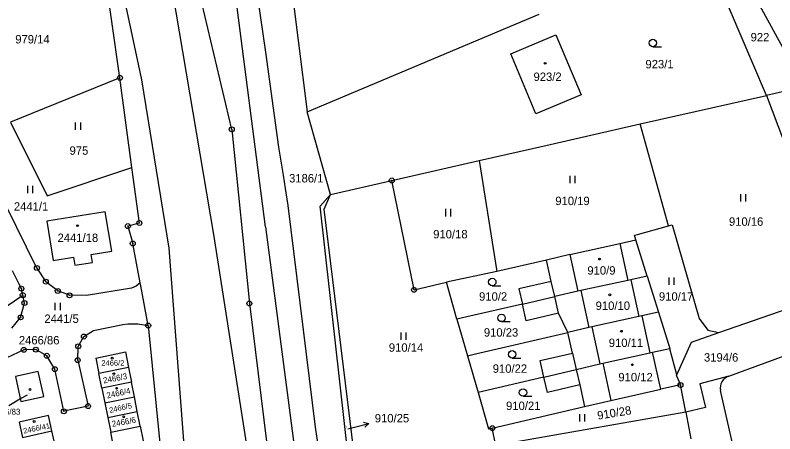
# Model space of a CAD drawing. Extents: x -736345 to -729997, y -1130177 to -1122501.
# Drawn here: x -733345 to -733191.4, y -1127571.2 to -1127486.6 of the extents above; entities that cross this region are included whole.
import ezdxf

# ---------------------------------------------------------------- set-up
doc = ezdxf.new("R2010")
doc.units = 0
for name, color, linetype in [('Vrstva 1', 7, 'Continuous'), ('Vrstva 10', 7, 'Continuous'), ('Vrstva 16', 7, 'Continuous'), ('Vrstva 18', 7, 'Continuous'), ('Vrstva 19', 7, 'Continuous'), ('Vrstva 25', 7, 'Continuous'), ('Vrstva 4', 7, 'Continuous')]:
    doc.layers.add(name, color=color, linetype=linetype)

msp = doc.modelspace()

# ---------------------------------------------------------------- linework, layer by layer
at = {"layer": 'Vrstva 1'}
for points in [[(-733301.2, -1127509.66), (-733310.3, -1127471.24)], [(-733200.3, -1127473.75), (-733185.45, -1127501.06)], [(-733323.81, -1127499.24), (-733327.23, -1127475.47)], [(-733294.28, -1127494.04), (-733296.98, -1127475.45)], [(-733195.81, -1127496.33), (-733204.85, -1127475.11)], [(-733289.62, -1127477.2), (-733285.95, -1127506.12)], [(-733285.95, -1127506.12), (-733239.06, -1127486.36)], [(-733244.79, -1127494.36), (-733235.65, -1127490.52)], [(-733235.65, -1127490.52), (-733230.53, -1127502.67)], [(-733291.7, -1127513.26), (-733294.28, -1127494.04)], [(-733239.67, -1127506.53), (-733244.79, -1127494.36)], [(-733193.06, -1127502.79), (-733195.81, -1127496.33)], [(-733323.81, -1127499.24), (-733341.66, -1127506.49)], [(-733321.39, -1127517.36), (-733323.81, -1127499.24)], [(-733185.45, -1127501.06), (-733193.06, -1127502.79)], [(-733230.53, -1127502.67), (-733239.67, -1127506.53)], [(-733218.57, -1127508.58), (-733193.06, -1127502.79)], [(-733193.06, -1127502.79), (-733178.14, -1127542.26)], [(-733341.66, -1127506.49), (-733345.96, -1127508.19)], [(-733281.24, -1127522.82), (-733285.95, -1127506.12)], [(-733345.96, -1127508.19), (-733338.54, -1127523.08)], [(-733237.7, -1127512.93), (-733218.57, -1127508.58)], [(-733212.85, -1127529.17), (-733218.57, -1127508.58)], [(-733301.2, -1127509.66), (-733297.64, -1127544.88)], [(-733290.75, -1127518.9), (-733291.7, -1127513.26)], [(-733251.18, -1127515.99), (-733237.7, -1127512.93)], [(-733340.6, -1127537.7), (-733351.02, -1127516.8)], [(-733268.83, -1127520), (-733251.18, -1127515.99)], [(-733251.18, -1127515.99), (-733247.58, -1127538.44)], [(-733338.54, -1127523.08), (-733321.39, -1127517.36)], [(-733319.88, -1127528.61), (-733321.39, -1127517.36)], [(-733290.33, -1127521.63), (-733290.75, -1127518.9)], [(-733281.24, -1127522.82), (-733268.83, -1127520)], [(-733264.34, -1127542.1), (-733268.83, -1127520)], [(-733289.76, -1127525.07), (-733290.33, -1127521.63)], [(-733283.29, -1127525.21), (-733281.24, -1127522.82)], [(-733282.53, -1127525.78), (-733281.24, -1127522.82)], [(-733326.79, -1127526.36), (-733338.6, -1127528.26)], [(-733325.47, -1127534.29), (-733326.79, -1127526.36)], [(-733284.29, -1127569.9), (-733289.76, -1127525.07)], [(-733277.3, -1127578.79), (-733283.29, -1127525.21)], [(-733276.02, -1127578.56), (-733282.53, -1127525.78)], [(-733338.6, -1127528.26), (-733337.32, -1127536.17)], [(-733319.88, -1127528.61), (-733322.2, -1127529.23)], [(-733322.2, -1127529.23), (-733321.22, -1127532.75)], [(-733219.11, -1127530.9), (-733212.85, -1127529.17)], [(-733212.85, -1127529.17), (-733212.14, -1127528.97)], [(-733212.14, -1127528.97), (-733206.65, -1127547.88)], [(-733219.76, -1127531.08), (-733219.11, -1127530.9)], [(-733219.47, -1127532.01), (-733219.76, -1127531.08)], [(-733222.7, -1127532.73), (-733219.47, -1127532.01)], [(-733217.18, -1127539.35), (-733219.47, -1127532.01)], [(-733319.72, -1127540.72), (-733321.22, -1127532.75)], [(-733232.8, -1127534.99), (-733222.7, -1127532.73)], [(-733337.32, -1127536.17), (-733333.17, -1127535.54)], [(-733333.17, -1127535.54), (-733332.93, -1127537.14)], [(-733329.61, -1127534.95), (-733325.47, -1127534.29)], [(-733329.35, -1127536.57), (-733329.61, -1127534.95)], [(-733232.8, -1127534.99), (-733237.55, -1127536.1)], [(-733332.93, -1127537.14), (-733329.35, -1127536.57)], [(-733237.55, -1127536.1), (-733247.58, -1127538.44)], [(-733236.57, -1127540.42), (-733237.55, -1127536.1)], [(-733344.18, -1127541), (-733345.53, -1127538.29)], [(-733340.6, -1127537.7), (-733338.8, -1127540.47)], [(-733247.58, -1127538.44), (-733257.79, -1127540.57)], [(-733221.07, -1127540.2), (-733230.6, -1127542.28)], [(-733220.48, -1127540.07), (-733221.07, -1127540.2)], [(-733217.18, -1127539.35), (-733220.48, -1127540.07)], [(-733217.18, -1127539.35), (-733214.9, -1127546.65)], [(-733343.75, -1127541.87), (-733344.18, -1127541)], [(-733343.46, -1127543.21), (-733343.75, -1127541.87)], [(-733336.38, -1127542.34), (-733338.8, -1127540.47)], [(-733321.45, -1127541.79), (-733330.57, -1127543.28)], [(-733320.53, -1127541.38), (-733321.45, -1127541.79)], [(-733319.72, -1127540.72), (-733320.53, -1127541.38)], [(-733319.6, -1127541.33), (-733319.72, -1127540.72)], [(-733318.09, -1127549.34), (-733319.6, -1127541.33)], [(-733264.34, -1127542.1), (-733257.79, -1127540.57)], [(-733255.65, -1127548.04), (-733257.79, -1127540.57)], [(-733236.57, -1127540.42), (-733243.12, -1127541.94)], [(-733357.22, -1127552.48), (-733343.46, -1127543.21)], [(-733343.13, -1127544.78), (-733343.46, -1127543.21)], [(-733334.01, -1127543.22), (-733336.38, -1127542.34)], [(-733330.57, -1127543.28), (-733334.01, -1127543.22)], [(-733243.12, -1127541.94), (-733242.43, -1127545)], [(-733231.18, -1127542.41), (-733235.87, -1127543.49)], [(-733230.6, -1127542.28), (-733231.18, -1127542.41)], [(-733202.72, -1127550.77), (-733178.14, -1127542.26)], [(-733343.89, -1127547.68), (-733343.13, -1127544.78)], [(-733297.64, -1127544.88), (-733292.42, -1127586.98)], [(-733242.43, -1127545), (-733235.87, -1127543.49)], [(-733242.43, -1127545), (-733253.65, -1127547.58)], [(-733241.66, -1127548.37), (-733242.43, -1127545)], [(-733200.69, -1127559.59), (-733163.94, -1127546.08)], [(-733345.65, -1127549.87), (-733343.89, -1127547.68)], [(-733253.65, -1127547.58), (-733255.65, -1127548.04)], [(-733255.65, -1127548.04), (-733253.52, -1127555.44)], [(-733235.1, -1127546.86), (-733241.66, -1127548.37)], [(-733233.23, -1127550.73), (-733235.1, -1127546.86)], [(-733218.85, -1127547.52), (-733228.38, -1127549.61)], [(-733218.27, -1127547.39), (-733218.85, -1127547.52)], [(-733214.9, -1127546.65), (-733218.27, -1127547.39)], [(-733214.9, -1127546.65), (-733212.62, -1127553.98)], [(-733206.65, -1127547.88), (-733204.93, -1127550.24)], [(-733329.17, -1127550.36), (-733323.21, -1127549.14)], [(-733323.21, -1127549.14), (-733322.2, -1127549)], [(-733322.2, -1127549), (-733320.19, -1127548.98)], [(-733320.19, -1127548.98), (-733318.09, -1127549.34)], [(-733318.09, -1127549.34), (-733313.97, -1127590.8)], [(-733331.1, -1127551.56), (-733329.17, -1127550.36)], [(-733251.93, -1127555.08), (-733233.23, -1127550.73)], [(-733228.97, -1127549.73), (-733233.23, -1127550.73)], [(-733232.28, -1127554.93), (-733233.23, -1127550.73)], [(-733228.38, -1127549.61), (-733228.97, -1127549.73)], [(-733208.22, -1127552.72), (-733202.72, -1127550.77)], [(-733204.93, -1127550.24), (-733202.72, -1127550.77)], [(-733332.25, -1127553.54), (-733331.1, -1127551.56)], [(-733332.35, -1127556.32), (-733332.25, -1127553.54)], [(-733216.09, -1127554.74), (-733212.62, -1127553.98)], [(-733212.62, -1127553.98), (-733212.6, -1127554.04)], [(-733211.16, -1127559.3), (-733212.6, -1127554.04)], [(-733211.16, -1127559.3), (-733208.22, -1127552.72)], [(-733343.26, -1127554.25), (-733346.67, -1127555.84)], [(-733340.81, -1127554.21), (-733343.26, -1127554.25)], [(-733338.58, -1127555.45), (-733340.81, -1127554.21)], [(-733336.98, -1127558.15), (-733338.58, -1127555.45)], [(-733328.68, -1127555.91), (-733322.71, -1127554.68)], [(-733322.71, -1127554.68), (-733322.08, -1127557.83)], [(-733253.52, -1127555.44), (-733251.93, -1127555.08)], [(-733253.52, -1127555.44), (-733251.39, -1127562.88)], [(-733238.83, -1127556.43), (-733232.28, -1127554.93)], [(-733226.16, -1127556.95), (-733216.63, -1127554.87)], [(-733216.63, -1127554.87), (-733216.09, -1127554.74)], [(-733332.35, -1127556.32), (-733330.26, -1127565.63)], [(-733328.68, -1127555.91), (-733328.05, -1127559.06)], [(-733238.08, -1127559.75), (-733238.83, -1127556.43)], [(-733231.53, -1127558.21), (-733226.75, -1127557.08)], [(-733226.75, -1127557.08), (-733226.16, -1127556.95)], [(-733340.32, -1127558.63), (-733344.96, -1127559.66)], [(-733339.22, -1127563.65), (-733340.32, -1127558.63)], [(-733335.15, -1127566.68), (-733336.98, -1127558.15)], [(-733322.08, -1127557.83), (-733328.05, -1127559.06)], [(-733322.08, -1127557.83), (-733321.49, -1127560.78)], [(-733238.08, -1127559.75), (-733231.53, -1127558.21)], [(-733344.96, -1127559.66), (-733343.86, -1127564.67)], [(-733327.46, -1127562), (-733328.05, -1127559.06)], [(-733238.08, -1127559.75), (-733251.39, -1127562.88)], [(-733237.37, -1127562.84), (-733238.08, -1127559.75)], [(-733211.26, -1127559.53), (-733211.16, -1127559.3)], [(-733211.26, -1127559.53), (-733210.45, -1127561.35)], [(-733200.69, -1127559.59), (-733206.56, -1127561.15), (-733205.42, -1127565.92), (-733209.39, -1127566.85)], [(-733321.49, -1127560.78), (-733327.46, -1127562)], [(-733320.9, -1127563.75), (-733321.49, -1127560.78)], [(-733230.82, -1127561.35), (-733237.37, -1127562.84)], [(-733230.82, -1127561.35), (-733229.83, -1127565.7)], [(-733210.45, -1127561.35), (-733214.42, -1127562.19)], [(-733209.39, -1127566.85), (-733210.45, -1127561.35)], [(-733327.46, -1127562), (-733326.86, -1127564.97)], [(-733251.39, -1127562.88), (-733249.28, -1127570.25)], [(-733224.53, -1127564.46), (-733214.42, -1127562.19)], [(-733198.38, -1127579.97), (-733202.34, -1127562.45)], [(-733343.86, -1127564.67), (-733339.22, -1127563.65)], [(-733326.86, -1127564.97), (-733320.9, -1127563.75)], [(-733320.31, -1127566.72), (-733320.9, -1127563.75)], [(-733229.83, -1127565.7), (-733224.53, -1127564.46)], [(-733330.26, -1127565.63), (-733335.15, -1127566.68)], [(-733326.86, -1127564.97), (-733326.27, -1127567.93)], [(-733248.5, -1127570.07), (-733229.83, -1127565.7)], [(-733338.28, -1127567.5), (-733344.21, -1127568.84)], [(-733337.57, -1127570.63), (-733338.28, -1127567.5)], [(-733326.27, -1127567.93), (-733320.31, -1127566.72)], [(-733326.27, -1127567.93), (-733325.67, -1127570.89)], [(-733319.72, -1127569.68), (-733320.31, -1127566.72)], [(-733209.39, -1127566.85), (-733247.81, -1127573.6)], [(-733209.39, -1127566.85), (-733208.34, -1127572.25)], [(-733344.21, -1127568.84), (-733343.5, -1127571.97)], [(-733343.5, -1127571.97), (-733337.57, -1127570.63)], [(-733336.9, -1127573.58), (-733337.57, -1127570.63)], [(-733325.67, -1127570.89), (-733319.72, -1127569.68)], [(-733325.08, -1127573.85), (-733325.67, -1127570.89)], [(-733319.72, -1127569.68), (-733319.13, -1127572.65)], [(-733282, -1127585.15), (-733284.29, -1127569.9)], [(-733249.28, -1127570.25), (-733248.5, -1127570.07)], [(-733247.81, -1127573.6), (-733248.5, -1127570.07)]]:
    msp.add_lwpolyline(points, dxfattribs=at)
msp.add_arc((-733199.973, -1127561.91), 2.428, 107.17471, 192.8411, dxfattribs=at)
at = {"layer": 'Vrstva 10'}
for points in [[(-733294.39, -1127529.35), (-733301.11, -1127477.15)], [(-733294.39, -1127529.35), (-733286.88, -1127586.59)]]:
    msp.add_lwpolyline(points, dxfattribs=at)
at = {"layer": 'Vrstva 16'}
for points in [[(-733342.6, -1127563.39), (-733343.69, -1127564.03)], [(-733277.73, -1127570.23), (-733276.37, -1127569.88)]]:
    msp.add_lwpolyline(points, dxfattribs=at)
at = {"layer": 'Vrstva 25'}
for points in [[(-733216.05, -1127492.95), (-733214.3, -1127492.95)], [(-733332.777, -1127509.755), (-733332.777, -1127508.255)], [(-733331.743, -1127509.755), (-733331.743, -1127508.255)], [(-733232.777, -1127520.535), (-733232.777, -1127519.035)], [(-733231.743, -1127520.535), (-733231.743, -1127519.035)], [(-733342.457, -1127522.585), (-733342.457, -1127521.085)], [(-733341.423, -1127522.585), (-733341.423, -1127521.085)], [(-733198.237, -1127524.245), (-733198.237, -1127522.745)], [(-733197.203, -1127524.245), (-733197.203, -1127522.745)], [(-733257.927, -1127527.265), (-733257.927, -1127525.765)], [(-733256.893, -1127527.265), (-733256.893, -1127525.765)], [(-733212.727, -1127541.095), (-733212.727, -1127539.595)], [(-733211.693, -1127541.095), (-733211.693, -1127539.595)], [(-733248.51, -1127541.28), (-733246.76, -1127541.28)], [(-733336.887, -1127546.255), (-733336.887, -1127544.755)], [(-733335.853, -1127546.255), (-733335.853, -1127544.755)], [(-733246.63, -1127548.55), (-733244.88, -1127548.55)], [(-733266.927, -1127552.225), (-733266.927, -1127550.725)], [(-733265.893, -1127552.225), (-733265.893, -1127550.725)], [(-733244.48, -1127555.91), (-733242.73, -1127555.91)], [(-733343.69, -1127564.03), (-733346.282, -1127565.539)], [(-733242.29, -1127563.64), (-733240.54, -1127563.64)], [(-733230.797, -1127568.755), (-733230.797, -1127567.255)], [(-733229.763, -1127568.755), (-733229.763, -1127567.255)], [(-733276.37, -1127569.88), (-733273.467, -1127569.124)], [(-733274.561, -1127568.893), (-733273.467, -1127569.124), (-733274.309, -1127569.86)]]:
    msp.add_lwpolyline(points, dxfattribs=at)
for centre, radius in [((-733216.05, -1127492.2), 0.75), ((-733237.81, -1127496.31), 0.175), ((-733323.81, -1127499.24), 0.5), ((-733323.81, -1127499.24), 0.032), ((-733301.2, -1127509.66), 0.5), ((-733301.2, -1127509.66), 0.032), ((-733268.83, -1127520), 0.5), ((-733268.83, -1127520), 0.032), ((-733332.38, -1127529.13), 0.175), ((-733322.2, -1127529.23), 0.5), ((-733322.2, -1127529.23), 0.032), ((-733319.88, -1127528.61), 0.5), ((-733319.88, -1127528.61), 0.032), ((-733321.22, -1127532.75), 0.5), ((-733321.22, -1127532.75), 0.032), ((-733226.82, -1127535.89), 0.175), ((-733340.6, -1127537.7), 0.5), ((-733340.6, -1127537.7), 0.032), ((-733338.8, -1127540.47), 0.5), ((-733248.51, -1127540.53), 0.75), ((-733343.75, -1127541.87), 0.5), ((-733343.75, -1127541.87), 0.032), ((-733338.8, -1127540.47), 0.032), ((-733336.38, -1127542.34), 0.5), ((-733264.34, -1127542.1), 0.5), ((-733343.46, -1127543.21), 0.5), ((-733343.46, -1127543.21), 0.032), ((-733336.38, -1127542.34), 0.032), ((-733334.01, -1127543.22), 0.5), ((-733334.01, -1127543.22), 0.032), ((-733264.34, -1127542.1), 0.032), ((-733224.74, -1127543.12), 0.175), ((-733343.13, -1127544.78), 0.5), ((-733343.13, -1127544.78), 0.032), ((-733297.64, -1127544.88), 0.5), ((-733297.64, -1127544.88), 0.032), ((-733343.89, -1127547.68), 0.5), ((-733343.89, -1127547.68), 0.032), ((-733246.63, -1127547.8), 0.75), ((-733318.09, -1127549.34), 0.5), ((-733318.09, -1127549.34), 0.032), ((-733331.1, -1127551.56), 0.5), ((-733222.39, -1127550.48), 0.175), ((-733331.1, -1127551.56), 0.032), ((-733343.26, -1127554.25), 0.5), ((-733340.81, -1127554.21), 0.5), ((-733340.81, -1127554.21), 0.032), ((-733332.25, -1127553.54), 0.5), ((-733332.25, -1127553.54), 0.032), ((-733343.26, -1127554.25), 0.032), ((-733338.58, -1127555.45), 0.5), ((-733338.58, -1127555.45), 0.032), ((-733244.48, -1127555.16), 0.75), ((-733332.35, -1127556.32), 0.5), ((-733332.35, -1127556.32), 0.032), ((-733325.38, -1127555.93), 0.175), ((-733220.18, -1127557.26), 0.175), ((-733336.98, -1127558.15), 0.5), ((-733336.98, -1127558.15), 0.032), ((-733325.04, -1127559.07), 0.175), ((-733324.48, -1127562.01), 0.175), ((-733210.45, -1127561.35), 0.5), ((-733210.45, -1127561.35), 0.032), ((-733342.01, -1127562.27), 0.175), ((-733242.29, -1127562.89), 0.75), ((-733335.15, -1127566.68), 0.5), ((-733330.26, -1127565.63), 0.5), ((-733330.26, -1127565.63), 0.032), ((-733335.15, -1127566.68), 0.032), ((-733323.06, -1127567.79), 0.175), ((-733341.16, -1127568.74), 0.175), ((-733248.5, -1127570.07), 0.5), ((-733248.5, -1127570.07), 0.032)]:
    msp.add_circle(centre, radius, dxfattribs=at)
at = {"layer": 'Vrstva 4'}
for points in [[(-733316.03, -1127465.24), (-733304.91, -1127530.9)], [(-733324.52, -1127475.91), (-733319.45, -1127499.67)], [(-733319.45, -1127499.67), (-733313.9, -1127533.67)], [(-733304.91, -1127530.9), (-733295.92, -1127588.16)], [(-733313.9, -1127533.67), (-733310.68, -1127576.23)], [(-733222.7, -1127532.73), (-733221.07, -1127540.2)], [(-733232.8, -1127534.99), (-733231.18, -1127542.41)], [(-733220.48, -1127540.07), (-733218.85, -1127547.52)], [(-733235.87, -1127543.49), (-733236.57, -1127540.42)], [(-733230.6, -1127542.28), (-733228.97, -1127549.73)], [(-733235.1, -1127546.86), (-733235.87, -1127543.49)], [(-733218.27, -1127547.39), (-733216.63, -1127554.87)], [(-733228.38, -1127549.61), (-733226.75, -1127557.08)], [(-733232.28, -1127554.93), (-733231.53, -1127558.21)], [(-733214.42, -1127562.19), (-733216.09, -1127554.74)], [(-733226.16, -1127556.95), (-733224.53, -1127564.46)], [(-733231.53, -1127558.21), (-733230.82, -1127561.35)]]:
    msp.add_lwpolyline(points, dxfattribs=at)

# ---------------------------------------------------------------- texts
at = {"layer": 'Vrstva 16'}
for s, height, p in [('2466/86', 1.7, (-733344.26, -1127553.15)), ('2466/83', 1.2, (-733349.743, -1127567.37)), ('910/25', 1.7, (-733272.27, -1127568.92))]:
    msp.add_text(s, height=height, dxfattribs=at).set_placement(p)
at = {"layer": 'Vrstva 18'}
for s, p in [('979/14', (-733344.98, -1127492.29)), ('923/1', (-733217.53, -1127497.33)), ('975', (-733334, -1127514.8)), ('3186/1', (-733289.61, -1127520.4)), ('910/19', (-733235.77, -1127524.98)), ('2441/1', (-733345.26, -1127526.1)), ('910/16', (-733200.65, -1127529.16)), ('910/18', (-733260.46, -1127531.71)), ('910/2', (-733251.18, -1127544.31)), ('910/17', (-733214.81, -1127544.31)), ('2441/5', (-733339.09, -1127548.8)), ('910/23', (-733250.21, -1127551.58)), ('910/14', (-733269.43, -1127554.63)), ('3194/6', (-733205.7, -1127556.63)), ('910/22', (-733248.42, -1127558.89)), ('910/21', (-733245.72, -1127566.41))]:
    msp.add_text(s, height=1.7, dxfattribs=at).set_placement(p)
for s, height, rotation, p in [('2466/5', 1.1, 12.3001, (-733325.848, -1127567.012)), ('910/28', 1.7, 9.50008, (-733227.136, -1127568.39)), ('910/25', 0.1, 95.70076, (-733277.948, -1127570.051))]:
    msp.add_text(s, height=height, rotation=rotation, dxfattribs=at).set_placement(p)
at = {"layer": 'Vrstva 19'}
for s, height, p in [('922', 1.7, (-733196.27, -1127491.88)), ('923/2', 1.7, (-733240.17, -1127499.88)), ('2441/18', 1.7, (-733336.428, -1127532.44)), ('910/9', 1.7, (-733229.28, -1127539.04)), ('910/10', 1.7, (-733227.61, -1127546.17)), ('910/11', 1.7, (-733224.95, -1127553.67)), ('2466/2', 1.1, (-733327.568, -1127557.44)), ('910/12', 1.7, (-733223.01, -1127560.62)), ('2466/83', 0.1, (-733342.4, -1127563.19))]:
    msp.add_text(s, height=height, dxfattribs=at).set_placement(p)
for s, height, rotation, p in [('2466/3', 1.2, 11.10009, (-733327.083, -1127561.056)), ('2466/4', 1.2, 12.3001, (-733326.378, -1127564.102)), ('2466/6', 1.2, 10.00008, (-733325.348, -1127569.829)), ('2466/41', 1.1, 11.80009, (-733343.246, -1127571.204))]:
    msp.add_text(s, height=height, rotation=rotation, dxfattribs=at).set_placement(p)

doc.saveas('drawing.dxf')
